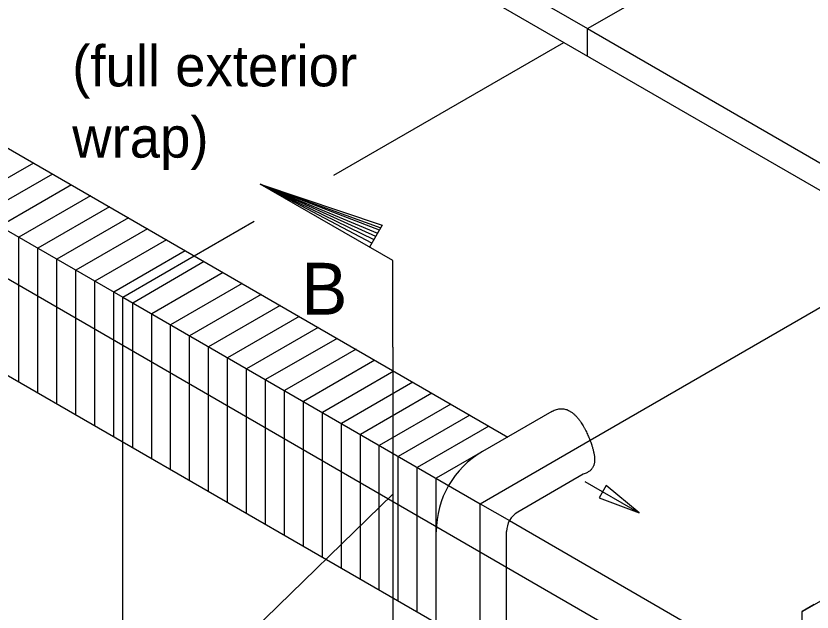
# Model space of a CAD drawing. Extents: x 10050 to 10414, y 76434 to 76519.
# Drawn here: x 10225.05 to 10236.85, y 76488.59 to 76497.43 of the extents above; entities that cross this region are included whole.
import ezdxf

# ---------------------------------------------------------------- set-up
doc = ezdxf.new("R2010")
doc.units = 0
for name, color, linetype in [('Patterning', 7, 'Continuous'), ('PlotBorder_dp', 7, 'Continuous'), ('SheetLines_dp', 7, 'Continuous'), ('SubStrConc_h', 7, 'Continuous'), ('TextMisc', 7, 'Continuous')]:
    doc.layers.add(name, color=color, linetype=linetype)

msp = doc.modelspace()

# ---------------------------------------------------------------- linework, layer by layer
at = {"layer": 'Patterning'}
for p, q in [((10230.326, 76494.061), (10228.667, 76494.937)), ((10228.667, 76494.937), (10230.356, 76494.113)), ((10230.383, 76494.16), (10228.667, 76494.937)), ((10228.667, 76494.937), (10230.411, 76494.208)), ((10230.436, 76494.251), (10228.667, 76494.937)), ((10228.667, 76494.937), (10230.456, 76494.286)), ((10230.635, 76493.801), (10228.667, 76494.937)), ((10228.667, 76494.937), (10230.478, 76494.325)), ((10230.478, 76494.325), (10230.291, 76494)), ((10230.635, 76492.517), (10230.635, 76493.801)), ((10230.635, 76492.517), (10230.635, 76488.164)), ((10233.486, 76490.526), (10234.288, 76490.063)), ((10220.452, 76480.436), (10230.635, 76490.34))]:
    msp.add_line(p, q, dxfattribs=at)
msp.add_lwpolyline([(10234.288, 76490.063), (10233.8, 76490.467), (10233.694, 76490.283)], close=True, dxfattribs=at)
at = {"layer": 'PlotBorder_dp'}
for p, q in [((10233.524, 76497.24), (10240.064, 76501.016)), ((10228.22, 76500.302), (10233.524, 76497.24)), ((10227.867, 76500.098), (10233.17, 76497.036)), ((10233.524, 76497.24), (10238.827, 76494.178)), ((10233.524, 76496.832), (10233.524, 76497.24)), ((10236.706, 76488.6), (10251.709, 76497.262)), ((10229.759, 76495.066), (10233.17, 76497.036)), ((10233.17, 76497.036), (10238.473, 76493.974)), ((10227.69, 76493.872), (10228.58, 76494.386)), ((10233.563, 76491.139), (10238.473, 76493.974)), ((10226.63, 76485.707), (10226.63, 76491.116)), ((10232.365, 76489.948), (10235.968, 76487.868)), ((10232.322, 76489.258), (10235.349, 76487.511)), ((10236.883, 76488.702), (10236.706, 76488.6)), ((10236.883, 76488.702), (10236.706, 76488.6)), ((10236.706, 76488.294), (10236.706, 76488.6))]:
    msp.add_line(p, q, dxfattribs=at)
at = {"layer": 'SubStrConc_h'}
for p, q in [((10216.023, 76498.669), (10232.322, 76489.258)), ((10222.381, 76495.712), (10226.63, 76493.259)), ((10226.63, 76493.259), (10227.69, 76493.872)), ((10226.63, 76493.259), (10231.933, 76490.198)), ((10226.63, 76491.116), (10226.63, 76493.259)), ((10231.933, 76490.198), (10233.563, 76491.139)), ((10231.933, 76490.198), (10232.365, 76489.948)), ((10231.933, 76487.397), (10231.933, 76490.198))]:
    msp.add_line(p, q, dxfattribs=at)
at = {"layer": 'TextMisc'}
for p, q in [((10222.387, 76496.934), (10232.34, 76491.187)), ((10225.307, 76495.248), (10224.247, 76494.635)), ((10225.589, 76495.085), (10224.528, 76494.473)), ((10225.87, 76494.923), (10224.809, 76494.31)), ((10226.151, 76494.76), (10225.091, 76494.148)), ((10226.433, 76494.598), (10225.372, 76493.986)), ((10226.714, 76494.435), (10225.653, 76493.823)), ((10226.995, 76494.273), (10225.935, 76493.661)), ((10225.091, 76492.005), (10225.091, 76494.148)), ((10227.277, 76494.111), (10226.216, 76493.498)), ((10225.372, 76491.842), (10225.372, 76493.986)), ((10221.808, 76493.9), (10231.279, 76488.432)), ((10227.558, 76493.948), (10226.497, 76493.336)), ((10225.653, 76491.68), (10225.653, 76493.823)), ((10227.839, 76493.786), (10226.779, 76493.173)), ((10225.935, 76491.517), (10225.935, 76493.661)), ((10228.12, 76493.623), (10227.06, 76493.011)), ((10226.216, 76491.355), (10226.216, 76493.498)), ((10228.402, 76493.461), (10227.341, 76492.849)), ((10226.497, 76491.193), (10226.497, 76493.336)), ((10228.683, 76493.299), (10227.622, 76492.686)), ((10226.779, 76491.03), (10226.779, 76493.173)), ((10228.964, 76493.136), (10227.904, 76492.524)), ((10227.06, 76490.868), (10227.06, 76493.011)), ((10229.246, 76492.974), (10228.185, 76492.361)), ((10227.341, 76490.705), (10227.341, 76492.849)), ((10229.527, 76492.811), (10228.466, 76492.199)), ((10227.622, 76490.543), (10227.622, 76492.686)), ((10229.808, 76492.649), (10228.748, 76492.037)), ((10227.904, 76490.381), (10227.904, 76492.524)), ((10230.09, 76492.487), (10229.029, 76491.874)), ((10228.185, 76490.218), (10228.185, 76492.361)), ((10230.371, 76492.324), (10229.31, 76491.712)), ((10228.466, 76490.056), (10228.466, 76492.199)), ((10230.652, 76492.162), (10229.592, 76491.549)), ((10228.748, 76489.893), (10228.748, 76492.037)), ((10230.933, 76491.999), (10229.873, 76491.387)), ((10229.029, 76489.731), (10229.029, 76491.874)), ((10231.215, 76491.837), (10230.154, 76491.225)), ((10229.31, 76489.569), (10229.31, 76491.712)), ((10231.496, 76491.675), (10230.435, 76491.062)), ((10229.592, 76489.406), (10229.592, 76491.549)), ((10231.777, 76491.512), (10230.717, 76490.9)), ((10232.994, 76491.565), (10231.965, 76490.971)), ((10229.873, 76489.244), (10229.873, 76491.387)), ((10232.059, 76491.35), (10230.998, 76490.737)), ((10230.154, 76489.081), (10230.154, 76491.225)), ((10230.435, 76488.919), (10230.435, 76491.062)), ((10231.965, 76490.971), (10231.279, 76490.575)), ((10230.717, 76488.757), (10230.717, 76490.9)), ((10230.998, 76488.594), (10230.998, 76490.737)), ((10231.279, 76489.783), (10231.279, 76490.575)), ((10233.461, 76490.636), (10232.489, 76490.074)), ((10231.279, 76487.676), (10231.279, 76489.783)), ((10232.322, 76487.696), (10232.322, 76489.785))]:
    msp.add_line(p, q, dxfattribs=at)
for centre, radius in [((10232.651, 76489.783), 1.372), ((10232.656, 76489.785), 0.333)]:
    msp.add_arc(centre, radius, 120, 180, dxfattribs=at)
msp.add_open_spline([(10232.994, 76491.565), (10233.176, 76491.67), (10233.431, 76491.475), (10233.561, 76491.142), (10233.654, 76490.905), (10233.63, 76490.689), (10233.461, 76490.636)], degree=4, dxfattribs=at)

# ---------------------------------------------------------------- texts
at = {"layer": 'Patterning'}
for s, p in [('(full exterior', (10225.881, 76496.384)), ('wrap)', (10225.881, 76495.328))]:
    msp.add_text(s, height=0.6048, dxfattribs=at).set_placement(p)
at = {"layer": 'SheetLines_dp'}
msp.add_text('B', height=0.768, dxfattribs=at).set_placement((10229.277, 76493.001))

doc.saveas('drawing.dxf')
